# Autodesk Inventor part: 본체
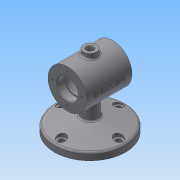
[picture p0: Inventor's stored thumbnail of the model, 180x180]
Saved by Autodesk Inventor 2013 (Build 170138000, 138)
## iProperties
Created: 2018-12
Part Number: 본체
Material: 일반
Document SubType Name: Modeling
Designer: Administrator
Density: 1 g/cm^3
Author: Administrator
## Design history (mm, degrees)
sketch "스케치1"
  geometry: L1 (-35, 16)-(-35, 30); L2 (-35, 30)-(35, 30); L3 (35, 30)-(35, 16); L4 (35, 16)-(23, 16); L5 (23, 16)-(23, 14); L6 (23, 14)-(20, 14); L7 (20, 14)-(20, 25); L8 (20, 25)-(-20, 25); L9 (-20, 25)-(-20, 14); L10 (-20, 14)-(-23, 14); L11 (-23, 14)-(-23, 16); L12 (-23, 16)-(-35, 16); L13 (-35, 0)-(35, 0); 4 further points
  constraints: 26 end point, 11 parallel, 3 midpoint, 2 collinear, 2 point on line, 2 vertical alignment, 1 coincident, 1 perpendicular, 1 vertical
  dimensions: "d0" = 28 diameter of L10 L13; "d2" = 32 diameter of L12 L13; "d3" = 60 diameter of L2 L13; "d4" = 50 diameter of L8 L13; "d5" = 70 distance of L1.end L2.end; "d6" = 12 distance of L11.end L1.start; "d7" = 12 distance of L3.end L4.end; "d9" = 40 distance of L7.end L8.end
revolve "회전1" sketch "스케치1" stored, may be unused: angle "d10" = 90 deg
node "작업 평면1"
sketch "스케치2"
  geometry: C1 r 55 at (0, 0); 1 further point
  constraints: 1 centre point, 1 coincident
  dimensions: "d12" = 110 diameter of C1
extrude "돌출1" join sketch "스케치2" distance "d13" = 11; taper "d14" = 0 deg
sketch "스케치3"
  geometry: C1 r 55 at (0, 0); 1 further point
  constraints: 1 centre point, 1 coincident
  dimensions: "d15" = 110 diameter of C1
extrude "돌출2" join sketch "스케치3" distance "d16" = 15; taper "d17" = -75 deg
sketch "스케치4"
  geometry: C1 r 12 at (0, 0); 1 further point
  constraints: 1 centre point, 1 coincident
  dimensions: "d18" = 24 diameter of C1
extrude "돌출3" join sketch "스케치4" stored distance "d19" = 0; taper "d20" = 0 deg
sketch "스케치5"
  geometry: 2 further points
  constraints: 1 vertical alignment
  dimensions: "d21" = 23 distance of point (0, 23) point (0, 0)
hole "구멍1" sketch "스케치5" at (0, 23) diameter "d22" = 3.242; stored, may be unused: countersink angle "d26" = 90 deg, drill point angle "d28" = 118 deg; dims "d23" = 8, "d24" = 4, "d25" = 2, "d27" = 10
node "작업 평면2"
sketch "스케치6"
  geometry: C1 r 10 at (0, 0); 1 further point
  constraints: 1 centre point, 1 coincident
  dimensions: "d33" = 20 diameter of C1
extrude "돌출4" join sketch "스케치6" stored distance "d34" = 15; taper "d35" = 0 deg
hole "구멍2" diameter "d38" = 10; stored, may be unused: countersink angle "d42" = 90 deg, drill point angle "d44" = 0 deg; dims "d36" = 10, "d37" = 10, "d39" = 8, "d40" = 4, "d41" = 2, "d43" = 10
sketch "스케치7"
  geometry: 2 further points
  constraints: 1 vertical alignment
  dimensions: "d45" = 44 distance of point (0, -44) point (0, 0)
hole "구멍3" sketch "스케치7" at (0, -44) diameter "d46" = 9; stored, may be unused: countersink angle "d50" = 90 deg, drill point angle "d52" = 0 deg; dims "d47" = 8, "d48" = 4, "d49" = 2, "d51" = 10
hole "구멍4" diameter "d55" = 14; stored, may be unused: countersink angle "d59" = 90 deg, drill point angle "d61" = 0 deg; dims "d53" = 10, "d54" = 10, "d56" = 8, "d57" = 4, "d58" = 2, "d60" = 10
node "작업 평면3"
sketch "스케치8"
  geometry: L1 (-35, -30)-(-35, 30) reference; 2 further points
  constraints: 1 other
  dimensions: "d66" = 35 distance from line of L1 point (0, 0); "d67" = 30 vertical distance of L1.end point (0, 0)
feature "엠보싱1" sketch "스케치8" dims "d0" = 28, "d2" = 32, "d3" = 60, "d4" = 50, "d5" = 70, "d6" = 12, "d7" = 12, "d9" = 40, "d68" = 0.5, "d69" = 0
fillet "모깎기1" dims "d70" = 3
fillet "모깎기2" dims "d71" = 0.3
chamfer "모따기1" distance "d72" = 1; stored, may be unused: second distance "d73" = 2, angle "d74" = 45 deg
node "솔리드1"
pattern_circular "원형 패턴1" dims angle "d30" = 360 deg
mirror "대칭1"
pattern_circular "원형 패턴2" dims angle "d63" = 360 deg
other parameters: "d11" = -75, "d32" = -112, "d65" = 173.25
